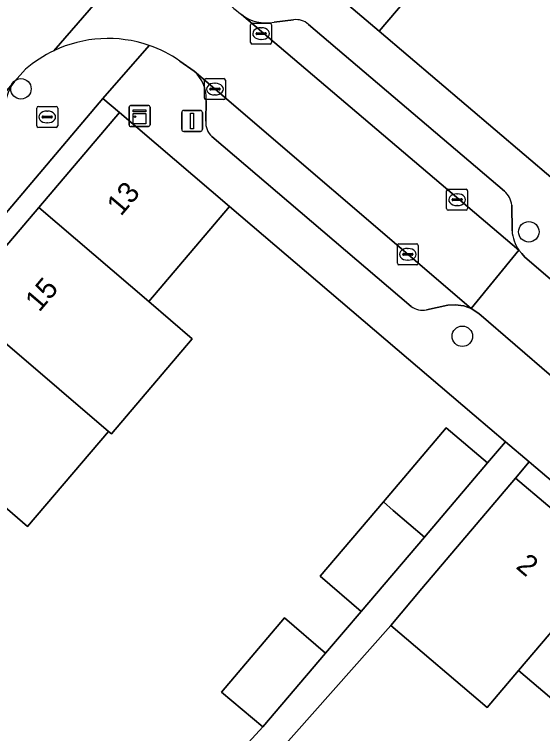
# Model space of a CAD drawing. Extents: x 162523 to 163266, y 381230 to 382050.
# Drawn here: x 163089.07 to 163114.31, y 381637.18 to 381671.51 of the extents above; entities that cross this region are included whole.
import ezdxf

# ---------------------------------------------------------------- set-up
doc = ezdxf.new("R2010")
doc.units = 0
for name, color, linetype in [('IMGEO_Boom', 7, 'Continuous'), ('IMGEO_Brandkraan', 7, 'Continuous'), ('IMGEO_Erf', 7, 'Continuous'), ('IMGEO_Kast', 7, 'Continuous'), ('IMGEO_Kolk', 7, 'Continuous'), ('IMGEO_Lichtmast', 7, 'Continuous'), ('IMGEO_Pand', 7, 'Continuous'), ('IMGEO_Pand_nummerreeks', 7, 'Continuous'), ('IMGEO_Parkeervlak_open', 7, 'Continuous'), ('IMGEO_Rijbaan_lokaal_open', 7, 'Continuous'), ('IMGEO_Voetpad_open', 7, 'Continuous')]:
    doc.layers.add(name, color=color, linetype=linetype)

msp = doc.modelspace()

# ---------------------------------------------------------------- linework, layer by layer
at = {"layer": 'IMGEO_Boom'}
for centre in [(163089.383, 381667.956), (163113.645, 381661.133), (163110.47, 381656.147)]:
    msp.add_circle(centre, 0.489, dxfattribs=at)
at = {"layer": 'IMGEO_Brandkraan'}
for p, q in [((163090.213, 381667.113), (163091.065, 381667.113)), ((163090.138, 381666.187), (163090.138, 381667.039)), ((163090.626, 381666.893), (163090.651, 381666.893)), ((163091.139, 381667.039), (163091.139, 381666.187)), ((163090.397, 381666.607), (163090.397, 381666.619)), ((163090.835, 381666.57), (163090.437, 381666.57)), ((163090.44, 381666.656), (163090.838, 381666.656)), ((163090.881, 381666.619), (163090.881, 381666.607)), ((163091.065, 381666.113), (163090.213, 381666.113)), ((163090.649, 381666.333), (163090.624, 381666.333))]:
    msp.add_line(p, q, dxfattribs=at)
for points in [[(163090.213, 381667.113), (163091.065, 381667.113)], [(163090.138, 381666.187), (163090.138, 381667.039)], [(163091.139, 381667.039), (163091.139, 381666.187)], [(163091.065, 381666.113), (163090.213, 381666.113)]]:
    msp.add_lwpolyline(points, dxfattribs=at)
for centre, radius, start, end in [((163090.215, 381667.037), 0.0765, 91.552, 178.448), ((163090.215, 381667.037), 0.0765, 91.552, 178.448), ((163091.063, 381667.037), 0.0765, 1.552, 88.448), ((163091.063, 381667.037), 0.0765, 1.552, 88.448), ((163090.437, 381666.616), 0.0403, 85.8775, 175.7526), ((163090.434, 381666.606), 0.0366, 178.938, 274.7102), ((163090.838, 381666.613), 0.043, 264.8664, 352.4533), ((163090.842, 381666.618), 0.0386, 1.7309, 96.639), ((163090.215, 381666.189), 0.0765, 181.552, 268.448), ((163090.215, 381666.189), 0.0765, 181.552, 268.448), ((163091.063, 381666.189), 0.0765, 271.552, 358.448), ((163091.063, 381666.189), 0.0765, 271.552, 358.448)]:
    msp.add_arc(centre, radius, start, end, dxfattribs=at)
for centre, major_axis, ratio, start_param, end_param in [((163090.625, 381666.613), (-0.387, 0.002), 0.722429, 4.712389, 7.853982), ((163090.65, 381666.613), (-0.39, 0.002), 0.717154, 1.570796, 4.712389)]:
    msp.add_ellipse(centre, major_axis=major_axis, ratio=ratio, start_param=start_param, end_param=end_param, dxfattribs=at)
at = {"layer": 'IMGEO_Erf'}
for points in [[(163132.906, 381679.956), (163136.779, 381684.471), (163139.655, 381687.823), (163141.902, 381685.895), (163142.866, 381687.018), (163129.847, 381698.192), (163126, 381693.663), (163122.134, 381689.113), (163124.245, 381687.324), (163120.381, 381682.775), (163118.27, 381684.564), (163114.404, 381680.014), (163110.538, 381675.463), (163106.497, 381670.706), (163117.58, 381661.297), (163121.655, 381666.095), (163120.341, 381667.209), (163121.496, 381668.569), (163124.884, 381665.692), (163129.421, 381671.346), (163127.168, 381673.267), (163129.032, 381675.44)], [(163082.504, 381653.225), (163086.368, 381657.761), (163090.233, 381662.298), (163094.086, 381666.82), (163093.302, 381667.488), (163069.973, 381639.961), (163070.687, 381639.356), (163074.773, 381644.152), (163078.638, 381648.688)], [(163113.665, 381650.148), (163113.013, 381649.38), (163117.64, 381645.457), (163122.186, 381641.602), (163126.733, 381637.748), (163131.468, 381633.733), (163132.115, 381634.496)], [(163126.994, 381628.455), (163122.248, 381632.479), (163117.702, 381636.334), (163113.155, 381640.188), (163111.661, 381638.433), (163107.047, 381642.345), (163101.543, 381636.141), (163106.289, 381632.182), (163108.281, 381634.52), (163108.335, 381634.475), (163108.685, 381634.183), (163112.927, 381630.644), (163109.418, 381626.539), (163110.156, 381625.898), (163111.734, 381627.773), (163115.503, 381624.601), (163113.878, 381622.67), (163114.07, 381622.503), (163115.609, 381624.322), (163115.668, 381624.271), (163115.77, 381624.185), (163120.125, 381620.494)]]:
    msp.add_lwpolyline(points, close=True, dxfattribs=at)
msp.add_lwpolyline([(163098.862, 381635.242), (163100.936, 381637.501), (163098.962, 381639.168), (163101.976, 381642.706), (163103.94, 381641.027), (163104.793, 381642.019), (163105.64, 381643.014), (163103.672, 381644.696), (163106.697, 381648.247), (163109.705, 381651.777), (163111.672, 381650.101), (163112.531, 381651.11), (163111.04, 381652.38), (163099.354, 381662.333), (163095.492, 381657.8), (163097.57, 381656.029), (163093.705, 381651.493), (163093.562, 381651.609), (163089.698, 381647.073), (163087.762, 381648.728)], dxfattribs=at)
at = {"layer": 'IMGEO_Kast'}
for p, q in [((163094.624, 381667.16), (163095.465, 381667.16)), ((163095.465, 381667.16), (163094.624, 381667.16)), ((163094.549, 381666.235), (163094.549, 381667.076)), ((163094.549, 381667.076), (163094.549, 381666.235)), ((163095.549, 381667.085), (163095.549, 381666.244)), ((163095.549, 381666.244), (163095.549, 381667.085)), ((163095.474, 381666.16), (163094.633, 381666.16)), ((163094.633, 381666.16), (163095.474, 381666.16))]:
    msp.add_line(p, q, dxfattribs=at)
for points in [[(163094.744, 381666.95), (163095.344, 381666.95), (163095.344, 381666.865), (163094.744, 381666.865), (163094.744, 381666.95)], [(163094.744, 381666.775), (163095.344, 381666.775), (163095.344, 381666.286), (163094.744, 381666.286), (163094.744, 381666.775)]]:
    msp.add_lwpolyline(points, dxfattribs=at)
msp.add_circle((163094.828, 381666.624), 0.0377, dxfattribs=at)
for centre, start, end in [((163094.627, 381667.082), 92.4484, 184.2845), ((163094.627, 381667.082), 92.4484, 184.2845), ((163095.471, 381667.082), 2.4484, 94.2845), ((163095.471, 381667.082), 2.4484, 94.2845), ((163094.627, 381666.238), 182.4484, 274.2845), ((163094.627, 381666.238), 182.4484, 274.2845), ((163095.471, 381666.238), 272.4484, 4.2845), ((163095.471, 381666.238), 272.4484, 4.2845)]:
    msp.add_arc(centre, 0.0779, start, end, dxfattribs=at)
at = {"layer": 'IMGEO_Kolk'}
for p, q in [((163100.356, 381670.166), (163100.356, 381671.018)), ((163100.431, 381671.092), (163101.283, 381671.092)), ((163100.844, 381670.872), (163100.869, 381670.872)), ((163101.357, 381671.018), (163101.357, 381670.166)), ((163100.615, 381670.586), (163100.615, 381670.598)), ((163101.053, 381670.549), (163100.655, 381670.549)), ((163100.658, 381670.635), (163101.056, 381670.635)), ((163101.099, 381670.598), (163101.099, 381670.586)), ((163100.867, 381670.312), (163100.842, 381670.312)), ((163101.283, 381670.092), (163100.431, 381670.092)), ((163098.151, 381667.518), (163098.151, 381668.37)), ((163098.226, 381668.444), (163099.078, 381668.444)), ((163098.639, 381668.224), (163098.664, 381668.224)), ((163099.152, 381668.37), (163099.152, 381667.518)), ((163098.41, 381667.938), (163098.41, 381667.95)), ((163098.848, 381667.901), (163098.45, 381667.901)), ((163098.453, 381667.987), (163098.851, 381667.987)), ((163098.894, 381667.95), (163098.894, 381667.938)), ((163099.078, 381667.444), (163098.226, 381667.444)), ((163098.662, 381667.664), (163098.637, 381667.664)), ((163109.721, 381662.239), (163109.721, 381663.091)), ((163109.796, 381663.165), (163110.648, 381663.165)), ((163110.722, 381663.091), (163110.722, 381662.239)), ((163109.98, 381662.659), (163109.98, 381662.671)), ((163110.023, 381662.708), (163110.421, 381662.708)), ((163110.209, 381662.945), (163110.234, 381662.945)), ((163110.464, 381662.671), (163110.464, 381662.659)), ((163110.418, 381662.622), (163110.02, 381662.622)), ((163110.232, 381662.385), (163110.207, 381662.385)), ((163110.648, 381662.165), (163109.796, 381662.165)), ((163107.367, 381659.632), (163107.367, 381660.484)), ((163107.442, 381660.558), (163108.294, 381660.558)), ((163107.855, 381660.338), (163107.88, 381660.338)), ((163108.368, 381660.484), (163108.368, 381659.632)), ((163107.626, 381660.052), (163107.626, 381660.064)), ((163108.064, 381660.015), (163107.666, 381660.015)), ((163107.669, 381660.101), (163108.067, 381660.101)), ((163108.11, 381660.064), (163108.11, 381660.052)), ((163108.294, 381659.558), (163107.442, 381659.558)), ((163107.878, 381659.778), (163107.853, 381659.778))]:
    msp.add_line(p, q, dxfattribs=at)
for points in [[(163100.356, 381670.166), (163100.356, 381671.018)], [(163100.431, 381671.092), (163101.283, 381671.092)], [(163101.357, 381671.018), (163101.357, 381670.166)], [(163101.283, 381670.092), (163100.431, 381670.092)], [(163098.151, 381667.518), (163098.151, 381668.37)], [(163098.226, 381668.444), (163099.078, 381668.444)], [(163099.152, 381668.37), (163099.152, 381667.518)], [(163099.078, 381667.444), (163098.226, 381667.444)], [(163109.721, 381662.239), (163109.721, 381663.091)], [(163109.796, 381663.165), (163110.648, 381663.165)], [(163110.722, 381663.091), (163110.722, 381662.239)], [(163110.648, 381662.165), (163109.796, 381662.165)], [(163107.367, 381659.632), (163107.367, 381660.484)], [(163107.442, 381660.558), (163108.294, 381660.558)], [(163108.368, 381660.484), (163108.368, 381659.632)], [(163108.294, 381659.558), (163107.442, 381659.558)]]:
    msp.add_lwpolyline(points, dxfattribs=at)
for centre, radius, start, end in [((163100.433, 381671.016), 0.0765, 91.552, 178.448), ((163100.433, 381671.016), 0.0765, 91.552, 178.448), ((163101.281, 381671.016), 0.0765, 1.552, 88.448), ((163101.281, 381671.016), 0.0765, 1.552, 88.448), ((163100.655, 381670.595), 0.0403, 85.8775, 175.7526), ((163100.652, 381670.585), 0.0366, 178.938, 274.7102), ((163101.056, 381670.592), 0.043, 264.8664, 352.4533), ((163101.06, 381670.597), 0.0386, 1.7309, 96.639), ((163100.433, 381670.168), 0.0765, 181.552, 268.448), ((163100.433, 381670.168), 0.0765, 181.552, 268.448), ((163101.281, 381670.168), 0.0765, 271.552, 358.448), ((163101.281, 381670.168), 0.0765, 271.552, 358.448), ((163098.228, 381668.368), 0.0765, 91.552, 178.448), ((163098.228, 381668.368), 0.0765, 91.552, 178.448), ((163099.076, 381668.368), 0.0765, 1.552, 88.448), ((163099.076, 381668.368), 0.0765, 1.552, 88.448), ((163098.45, 381667.947), 0.0403, 85.8775, 175.7526), ((163098.447, 381667.937), 0.0366, 178.938, 274.7102), ((163098.851, 381667.944), 0.043, 264.8664, 352.4533), ((163098.855, 381667.949), 0.0386, 1.7309, 96.639), ((163098.228, 381667.52), 0.0765, 181.552, 268.448), ((163098.228, 381667.52), 0.0765, 181.552, 268.448), ((163099.076, 381667.52), 0.0765, 271.552, 358.448), ((163099.076, 381667.52), 0.0765, 271.552, 358.448), ((163109.798, 381663.089), 0.0765, 91.552, 178.448), ((163109.798, 381663.089), 0.0765, 91.552, 178.448), ((163110.646, 381663.089), 0.0765, 1.552, 88.448), ((163110.646, 381663.089), 0.0765, 1.552, 88.448), ((163110.02, 381662.668), 0.0403, 85.8775, 175.7526), ((163110.017, 381662.658), 0.0366, 178.938, 274.7102), ((163110.421, 381662.665), 0.043, 264.8664, 352.4533), ((163110.425, 381662.67), 0.0386, 1.7309, 96.639), ((163109.798, 381662.241), 0.0765, 181.552, 268.448), ((163109.798, 381662.241), 0.0765, 181.552, 268.448), ((163110.646, 381662.241), 0.0765, 271.552, 358.448), ((163110.646, 381662.241), 0.0765, 271.552, 358.448), ((163107.444, 381660.482), 0.0765, 91.552, 178.448), ((163107.444, 381660.482), 0.0765, 91.552, 178.448), ((163108.292, 381660.482), 0.0765, 1.552, 88.448), ((163108.292, 381660.482), 0.0765, 1.552, 88.448), ((163107.666, 381660.061), 0.0403, 85.8775, 175.7526), ((163107.663, 381660.051), 0.0366, 178.938, 274.7102), ((163108.067, 381660.058), 0.043, 264.8664, 352.4533), ((163108.071, 381660.063), 0.0386, 1.7309, 96.639), ((163107.444, 381659.634), 0.0765, 181.552, 268.448), ((163107.444, 381659.634), 0.0765, 181.552, 268.448), ((163108.292, 381659.634), 0.0765, 271.552, 358.448), ((163108.292, 381659.634), 0.0765, 271.552, 358.448)]:
    msp.add_arc(centre, radius, start, end, dxfattribs=at)
for centre, major_axis, ratio, start_param, end_param in [((163100.843, 381670.592), (-0.387, 0.002), 0.722429, 4.712389, 7.853982), ((163100.868, 381670.592), (-0.39, 0.002), 0.717154, 1.570796, 4.712389), ((163098.638, 381667.944), (-0.387, 0.002), 0.722429, 4.712389, 7.853982), ((163098.663, 381667.944), (-0.39, 0.002), 0.717154, 1.570796, 4.712389), ((163110.208, 381662.665), (-0.387, 0.002), 0.722429, 4.712389, 7.853982), ((163110.233, 381662.665), (-0.39, 0.002), 0.717154, 1.570796, 4.712389), ((163107.854, 381660.058), (-0.387, 0.002), 0.722429, 4.712389, 7.853982), ((163107.879, 381660.058), (-0.39, 0.002), 0.717154, 1.570796, 4.712389)]:
    msp.add_ellipse(centre, major_axis=major_axis, ratio=ratio, start_param=start_param, end_param=end_param, dxfattribs=at)
at = {"layer": 'IMGEO_Lichtmast'}
for p, q in [((163097.063, 381666.024), (163097.063, 381666.824)), ((163097.063, 381666.824), (163097.063, 381666.024)), ((163097.163, 381666.924), (163097.953, 381666.924)), ((163097.953, 381666.924), (163097.163, 381666.924)), ((163098.053, 381666.824), (163098.053, 381666.024)), ((163098.053, 381666.024), (163098.053, 381666.824)), ((163097.953, 381665.924), (163097.163, 381665.924)), ((163097.163, 381665.924), (163097.953, 381665.924))]:
    msp.add_line(p, q, dxfattribs=at)
msp.add_lwpolyline([(163097.483, 381666.799), (163097.633, 381666.799), (163097.633, 381666.049), (163097.483, 381666.049), (163097.483, 381666.799)], dxfattribs=at)
for centre, start, end in [((163097.163, 381666.824), 90, 180), ((163097.163, 381666.824), 90, 180), ((163097.953, 381666.824), 0, 90), ((163097.953, 381666.824), 360, 90), ((163097.163, 381666.024), 180, 270), ((163097.163, 381666.024), 180, 270), ((163097.953, 381666.024), 270, 0), ((163097.953, 381666.024), 270, 0)]:
    msp.add_arc(centre, 0.1, start, end, dxfattribs=at)
at = {"layer": 'IMGEO_Pand'}
for points in [[(163110.538, 381675.463), (163105.261, 381679.936), (163101.218, 381675.181), (163106.497, 381670.706)], [(163090.233, 381662.298), (163095.492, 381657.8), (163099.354, 381662.333), (163094.086, 381666.82)], [(163086.368, 381657.761), (163093.562, 381651.609), (163093.705, 381651.493), (163097.57, 381656.029), (163095.492, 381657.8), (163090.233, 381662.298)], [(163086.368, 381657.761), (163082.504, 381653.225), (163087.762, 381648.728), (163089.698, 381647.073), (163093.562, 381651.609)], [(163111.672, 381650.101), (163109.705, 381651.777), (163106.697, 381648.247), (163107.174, 381647.839), (163108.663, 381646.565)], [(163117.64, 381645.457), (163113.013, 381649.38), (163108.538, 381644.103), (163107.047, 381642.345), (163111.661, 381638.433), (163113.155, 381640.188)], [(163108.663, 381646.565), (163107.174, 381647.839), (163106.697, 381648.247), (163103.672, 381644.696), (163105.64, 381643.014)], [(163117.64, 381645.457), (163113.155, 381640.188), (163117.702, 381636.334), (163122.186, 381641.602)], [(163098.962, 381639.168), (163100.936, 381637.501), (163103.94, 381641.027), (163101.976, 381642.706)]]:
    msp.add_lwpolyline(points, close=True, dxfattribs=at)
at = {"layer": 'IMGEO_Parkeervlak_open'}
for points in [[(163099.914, 381671.506), (163113.175, 381660.25)], [(163102.412, 381671.25), (163101.473, 381671.139)], [(163112.479, 381663.078), (163103.122, 381671.034)], [(163108.763, 381657.416), (163109.776, 381657.625), (163110.132, 381657.651), (163110.543, 381657.6), (163110.895, 381657.469), (163097.662, 381668.793)], [(163089.068, 381668.301), (163070.746, 381646.776), (163068.898, 381644.606), (163067.142, 381642.543)], [(163098.23, 381667.405), (163098.213, 381666.406)], [(163098.505, 381665.68), (163108.027, 381657.575)], [(163112.845, 381661.182), (163112.83, 381662.396)]]:
    msp.add_lwpolyline(points, dxfattribs=at)
for centre, radius, start, end in [((163101.088, 381672.998), 1.898, 231.8003, 281.7064), ((163102.539, 381670.393), 0.866, 47.7086, 98.4492), ((163096.511, 381667.512), 1.723, 356.4508, 48.0601), ((163090.554, 381667.097), 1.913, 140.9923, 188.9693), ((163099.092, 381666.338), 0.882, 175.5717, 228.2486), ((163111.828, 381662.312), 1.005, 4.8054, 49.661), ((163114.756, 381661.334), 1.917, 184.552, 214.4438), ((163108.557, 381658.246), 0.855, 231.6785, 283.9406)]:
    msp.add_arc(centre, radius, start, end, dxfattribs=at)
at = {"layer": 'IMGEO_Rijbaan_lokaal_open'}
for points in [[(163098.985, 381679.926), (163113.05, 381696.497), (163110.354, 381698.823), (163094.918, 381680.596), (163079.904, 381662.933), (163079.764, 381662.769), (163068.08, 381649.049), (163070.746, 381646.776), (163089.068, 381668.301), (163089.601, 381668.89)], [(163097.712, 381677.554), (163090.958, 381669.776)], [(163090.958, 381669.776), (163097.712, 381677.554)], [(163096.977, 381669.284), (163097.662, 381668.793), (163110.895, 381657.469), (163113.175, 381660.25), (163099.914, 381671.506)]]:
    msp.add_lwpolyline(points, dxfattribs=at)
msp.add_lwpolyline([(163114.738, 381654.244), (163116.999, 381656.899), (163113.458, 381659.924), (163113.314, 381660.09), (163113.175, 381660.25), (163110.895, 381657.469), (163111.252, 381657.236)], close=True, dxfattribs=at)
for centre, radius, start, end in [((163103.685, 381676.569), 6.313, 211.1659, 233.3211), ((163093.543, 381664.334), 6.025, 70.9917, 115.4029), ((163093.566, 381664.378), 5.975, 55.187, 71.0618), ((163093.516, 381664.375), 5.976, 115.348, 130.9339)]:
    msp.add_arc(centre, radius, start, end, dxfattribs=at)
at = {"layer": 'IMGEO_Voetpad_open'}
for points in [[(163159.568, 381625.629), (163157.339, 381627.523), (163151.263, 381632.684), (163148.238, 381635.254), (163139.137, 381642.985), (163136.111, 381645.555), (163133.063, 381648.145), (163127.011, 381653.286), (163123.962, 381655.875), (163120.755, 381658.6), (163119.655, 381659.534), (163118.125, 381660.834), (163117.58, 381661.297), (163106.497, 381670.706), (163101.218, 381675.181), (163100.456, 381675.828), (163098.283, 381673.302)], [(163101.473, 381671.139), (163102.412, 381671.25)], [(163103.122, 381671.034), (163112.479, 381663.078)], [(163093.302, 381667.488), (163095.505, 381670.03)], [(163095.505, 381670.03), (163093.302, 381667.488), (163094.086, 381666.82), (163099.354, 381662.333), (163111.04, 381652.38), (163112.531, 381651.11), (163113.665, 381650.148), (163132.115, 381634.496), (163132.812, 381633.934)], [(163097.662, 381668.793), (163096.977, 381669.284)], [(163089.601, 381668.89), (163089.068, 381668.301)], [(163058.231, 381626.174), (163059.268, 381627.393), (163065.516, 381634.738), (163067.361, 381636.896), (163069.021, 381638.837), (163069.973, 381639.961), (163093.302, 381667.488)], [(163098.213, 381666.406), (163098.23, 381667.405)], [(163108.027, 381657.575), (163098.505, 381665.68)], [(163112.83, 381662.396), (163112.845, 381661.182)], [(163113.175, 381660.25), (163113.314, 381660.09), (163113.458, 381659.924), (163116.999, 381656.899), (163117.413, 381656.545)], [(163114.738, 381654.244), (163111.252, 381657.236), (163110.895, 381657.469), (163110.543, 381657.6), (163110.132, 381657.651), (163109.776, 381657.625), (163108.763, 381657.416)], [(163088.678, 381622.137), (163089.235, 381621.665), (163089.392, 381621.85), (163099.963, 381634.278), (163101.543, 381636.141), (163107.047, 381642.345), (163108.538, 381644.103), (163113.013, 381649.38), (163113.665, 381650.148), (163112.531, 381651.11), (163111.672, 381650.101), (163108.663, 381646.565), (163105.64, 381643.014), (163104.793, 381642.019), (163103.94, 381641.027), (163100.936, 381637.501), (163098.862, 381635.242), (163096.958, 381633.008), (163096.919, 381633.042), (163092.92, 381628.605), (163088.877, 381624.118)]]:
    msp.add_lwpolyline(points, dxfattribs=at)
for centre, radius, start, end in [((163103.685, 381676.569), 6.313, 211.1659, 233.3211), ((163101.088, 381672.998), 1.898, 231.8003, 281.7064), ((163102.539, 381670.393), 0.866, 47.7086, 98.4492), ((163093.543, 381664.334), 6.025, 70.9917, 115.4029), ((163093.566, 381664.378), 5.975, 55.187, 71.0618), ((163093.516, 381664.375), 5.976, 115.348, 130.9339), ((163096.511, 381667.512), 1.723, 356.4508, 48.0601), ((163090.554, 381667.097), 1.913, 140.9923, 188.9693), ((163099.092, 381666.338), 0.882, 175.5717, 228.2486), ((163111.828, 381662.312), 1.005, 4.8054, 49.661), ((163114.756, 381661.334), 1.917, 184.552, 214.4438), ((163108.557, 381658.246), 0.855, 231.6785, 283.9406)]:
    msp.add_arc(centre, radius, start, end, dxfattribs=at)

# ---------------------------------------------------------------- texts
at = {"layer": 'IMGEO_Pand_nummerreeks'}
for s, rotation, p in [('13', 49.5694, (163094.157, 381661.844)), ('15', 49.5694, (163090.257, 381657.266)), ('2', 319.7096, (163112.987, 381645.101))]:
    msp.add_text(s, height=1, rotation=rotation, dxfattribs=at).set_placement(p)

doc.saveas('drawing.dxf')
